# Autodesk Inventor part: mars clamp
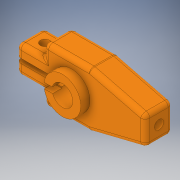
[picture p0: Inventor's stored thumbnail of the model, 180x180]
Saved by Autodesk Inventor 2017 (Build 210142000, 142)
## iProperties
Created: 2016-05
Part Number: mars clamp
Material: Generic
Document SubType Name: Modeling
Designer: Stan
Density: 1 g/cm^3
Appearance: Orange
Author: Stan
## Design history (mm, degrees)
sketch "Sketch1"
  geometry: L1 (-9.525, 9.525)-(6.35, 9.525); L2 (6.35, -9.463)-(-9.525, -9.463); L3 (25.4, 4.763)-(25.4, -4.763); L4 (25.4, -4.763)-(6.35, -9.463); L5 (25.4, 4.763)-(6.35, 9.525); L6 (-9.525, 9.525)-(-9.525, 4.763); L7 (-9.525, 4.763)-(-19.05, 4.762); L8 (-19.05, -4.7)-(-9.525, -4.7); L9 (-9.525, -4.7)-(-9.525, -9.463); L10 (-3.49, 0.762)-(-19.05, 0.762); L11 (-3.49, -0.762)-(-19.05, -0.762); L12 (-19.05, -4.7)-(-19.05, -0.762); L13 (-19.05, 0.762)-(-19.05, 4.762); A1 r 3.572 centre (0, 0) between (-3.49, -0.762) and (-3.49, 0.762); 1 further point
  constraints: 26 end point, 4 perpendicular, 2 point on circle, 2 point on line, 2 vertical, 1 centre point, 1 coincident, 1 horizontal, 1 parallel
  dimensions: "d1" = 9.525 distance from line of L1 point (0, 0); "d2" = 25.4 horizontal distance of L3.end point (0, 0); "d4" = 9.525 distance of L3.start L3.end; "d5" = 4.7625 vertical distance of point (0, 0) L3.start; "d7" = 7.14375 diameter of A1; "d8" = 19.05 horizontal distance of L8.start point (0, 0); "d11" = 9.525 distance from line of point (0, 0) L6; "d12" = 19.05 distance from line of point (0, 0) L13; "d14" = 1.524 distance between parallel lines of L11 L10; "d15" = 0.762 distance from line of L10 point (0, 0); "d16" = 15.875 distance of L1.start L1.end; "d17" = 15.875 distance of L2.start L2.end; "d18" = 4.7625 distance between parallel lines of L2 L8; "d19" = 4.7625 distance between parallel lines of L7 L1
extrude "Extrusion1" new body sketch "Sketch1" distance "d20" = 9.525; taper "d21" = 0 deg
fillet "Fillet1" dims "d22" = 1.5875
sketch "Sketch2"
  geometry: C1 r 1.587 at (3.175, 3.519); 1 further point
  constraints: 1 centre point
  dimensions: "d23" = 3.175 diameter of C1
extrude "Extrusion2" cut sketch "Sketch2" distance "d24" = 15.875; taper "d25" = 0 deg
sketch "Sketch3"
  geometry: L1 (-1.587, 6.35)-(-1.588, 0) reference; C1 r 1.587 at (3.492, 3.175); 1 further point
  constraints: 1 centre point
  dimensions: "d26" = 3.175 diameter of C1; "d27" = 5.08 distance from line of C1.centre L1
extrude "Extrusion3" cut sketch "Sketch3" distance "d28" = 9.525; taper "d29" = 0 deg
fillet "Fillet2" dims "d30" = 1.5875
fillet "Fillet3" dims "d31" = 1.5875
sketch "Sketch4"
  geometry: L1 (-3.49, 0.762)-(-6.304, 0.762); L2 (-17.462, 0.762)-(-3.49, 0.762) reference; L3 (-3.384, -1.143)-(-6.246, -1.143); A1 r 6.35 centre (0, 0) between (-6.246, -1.143) and (-6.304, 0.762); A2 r 3.572 centre (0, 0) between (-3.384, -1.143) and (-3.49, 0.762); 1 further point
  constraints: 5 end point, 4 point on circle, 2 centre point, 2 coincident, 1 parallel, 1 point on line
  dimensions: "d32" = 12.7 diameter of A1
extrude "Extrusion4" join sketch "Sketch4" distance "d33" = 3.175; taper "d34" = 0 deg
body "Solid1"
